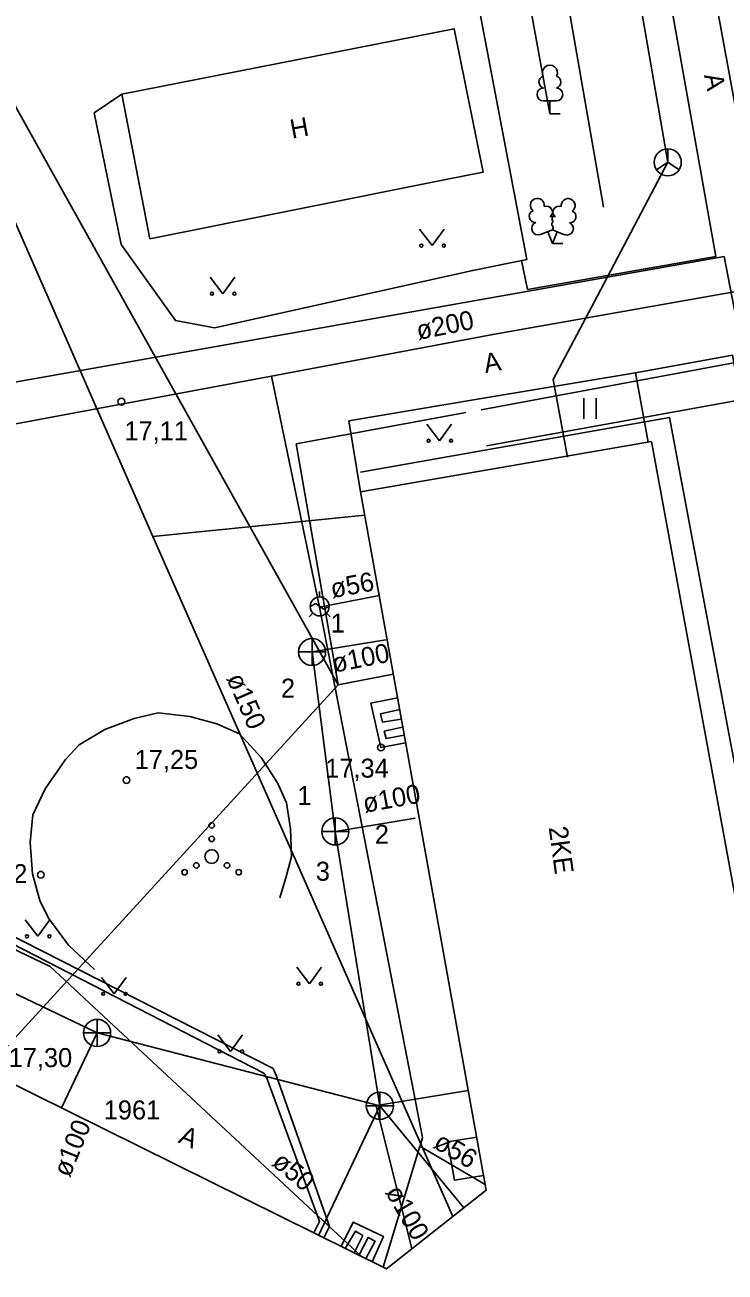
# Model space of a CAD drawing. Extents: x 713540 to 713867, y 6589774 to 6590061.
# Drawn here: x 713641.99 to 713667.81, y 6589963.85 to 6590009.83 of the extents above; entities that cross this region are included whole.
import ezdxf

# ---------------------------------------------------------------- set-up
doc = ezdxf.new("R2010")
doc.units = 0
for name, color, linetype in [('AED', 7, 'Continuous'), ('HALJASTUS', 7, 'Continuous'), ('HOONE', 7, 'Continuous'), ('HOONEDET', 7, 'Continuous'), ('KAEVU_NR', 7, 'Continuous'), ('KKAEV', 7, 'Continuous'), ('KORGUS', 7, 'Continuous'), ('KTRASS', 7, 'Continuous'), ('MPKAABEL', 7, 'Continuous'), ('PUU', 7, 'Continuous'), ('SIKAEV', 7, 'Continuous'), ('SITRASS', 7, 'Continuous'), ('TEE', 7, 'Continuous'), ('TORU NR', 7, 'Continuous'), ('TTRASS', 7, 'Continuous'), ('VTRASS', 7, 'Continuous'), ('Слой 1', 7, 'Continuous')]:
    doc.layers.add(name, color=color, linetype=linetype)

msp = doc.modelspace()

# ---------------------------------------------------------------- linework, layer by layer
at = {"layer": 'AED'}
for points in [[(713663.323, 6590003.114), (713657.209, 6590038.24)], [(713664.505, 6589997.008), (713664.975, 6589994.447)]]:
    msp.add_lwpolyline(points, dxfattribs=at)
at = {"layer": 'HALJASTUS'}
for p, q in [((713656.547, 6590002.297), (713657.01, 6590001.69)), ((713657.01, 6590001.69), (713657.456, 6590002.297)), ((713648.827, 6590000.527), (713649.29, 6589999.92)), ((713649.29, 6589999.92), (713649.736, 6590000.527)), ((713662.6, 6589996.063), (713662.6, 6589995.302)), ((713663.055, 6589996.063), (713663.055, 6589995.302)), ((713656.815, 6589995.104), (713657.278, 6589994.497)), ((713657.278, 6589994.497), (713657.724, 6589995.104)), ((713642.007, 6589976.837), (713642.47, 6589976.23)), ((713642.47, 6589976.23), (713642.916, 6589976.837)), ((713652.017, 6589975.087), (713652.48, 6589974.48)), ((713652.48, 6589974.48), (713652.926, 6589975.087)), ((713644.817, 6589974.717), (713645.28, 6589974.11)), ((713645.28, 6589974.11), (713645.726, 6589974.717)), ((713649.107, 6589972.597), (713649.57, 6589971.99)), ((713649.57, 6589971.99), (713650.016, 6589972.597))]:
    msp.add_line(p, q, dxfattribs=at)
msp.add_lwpolyline([(713655.98, 6590036), (713661.349, 6590006.549)], dxfattribs=at)
for centre, radius in [((713656.609, 6590001.69), 0.055), ((713657.438, 6590001.69), 0.055), ((713648.889, 6589999.92), 0.055), ((713649.718, 6589999.92), 0.055), ((713656.877, 6589994.497), 0.055), ((713657.706, 6589994.497), 0.055), ((713648.88, 6589980.32), 0.1), ((713648.88, 6589979.82), 0.1), ((713648.88, 6589979.17), 0.25), ((713648.315, 6589978.845), 0.1), ((713649.445, 6589978.845), 0.1), ((713647.88, 6589978.595), 0.1), ((713649.88, 6589978.595), 0.1), ((713642.069, 6589976.23), 0.055), ((713642.898, 6589976.23), 0.055), ((713652.079, 6589974.48), 0.055), ((713652.908, 6589974.48), 0.055), ((713644.879, 6589974.11), 0.055), ((713645.708, 6589974.11), 0.055), ((713649.169, 6589971.99), 0.055), ((713649.998, 6589971.99), 0.055)]:
    msp.add_circle(centre, radius, dxfattribs=at)
at = {"layer": 'HOONE'}
for p, q in [((713652.86, 6589988.74), (713652.86, 6589988.937)), ((713652.613, 6589988.143), (713652.473, 6589988.003)), ((713652.51, 6589988.388), (713652.721, 6589988.494)), ((713652.721, 6589988.494), (713652.999, 6589988.286)), ((713652.999, 6589988.286), (713653.21, 6589988.392)), ((713653.107, 6589988.143), (713653.247, 6589988.003))]:
    msp.add_line(p, q, dxfattribs=at)
for points in [[(713657.508, 6590004.134), (713646.604, 6590001.948), (713645.573, 6590007.272), (713657.824, 6590009.688), (713658.886, 6590004.404), (713657.508, 6590004.134)], [(713641.66, 6589995.12), (713651.08, 6589996.88), (713659.244, 6589998.419), (713687.328, 6590003.385)], [(713652.86, 6589988.37), (713651.08, 6589996.88)], [(713665.097, 6589994.469), (713654.36, 6589992.62), (713659, 6589966.87), (713655.32, 6589963.97), (713631.86, 6589975.579), (713626.949, 6589965.568), (713655.111, 6589952.011), (713657.717, 6589953.998), (713658.827, 6589952.543), (713664.692, 6589957.048), (713664.664, 6589957.055), (713669.225, 6589960.582), (713668.167, 6589961.969), (713670.71, 6589963.909), (713665.097, 6589994.469)], [(713655.05, 6589988.79), (713652.86, 6589988.37)], [(713656.56, 6589968.5), (713656.65, 6589968.81), (713652.86, 6589988.37)], [(713655.2, 6589964.03), (713656.55, 6589968.5)], [(713658.96, 6589967.08), (713656.55, 6589968.5)]]:
    msp.add_lwpolyline(points, dxfattribs=at)
msp.add_circle((713652.86, 6589988.39), 0.35, dxfattribs=at)
at = {"layer": 'HOONEDET'}
for points in [[(713654.365, 6589993.337), (713665.759, 6589995.354), (713671.737, 6589963.499), (713669.522, 6589961.81), (713670.612, 6589960.382), (713665.868, 6589956.768), (713665.7, 6589956.808), (713658.611, 6589951.238), (713657.507, 6589952.685), (713655.117, 6589950.862), (713625.629, 6589965.327), (713631.231, 6589977.05), (713635.106, 6589975.077), (713639.12, 6589973.07)], [(713656.03, 6589983.36), (713655.12, 6589983.19), (713654.75, 6589984.83), (713655.73, 6589985.02)], [(713655.81, 6589984.59), (713655.1, 6589984.43), (713655.18, 6589984.12), (713655.87, 6589984.24)], [(713655.92, 6589983.94), (713655.24, 6589983.79), (713655.31, 6589983.52), (713655.98, 6589983.65)], [(713658.9, 6589967.41), (713657.83, 6589967.24), (713657.57, 6589968.66), (713658.65, 6589968.83)], [(713654.8, 6589964.23), (713655.21, 6589965.16), (713654.09, 6589965.69), (713653.65, 6589964.8)], [(713654.13, 6589964.56), (713654.45, 6589965.2), (713654.18, 6589965.36), (713653.8, 6589964.72)], [(713654.56, 6589964.35), (713654.91, 6589964.99), (713654.65, 6589965.13), (713654.3, 6589964.47)]]:
    msp.add_lwpolyline(points, dxfattribs=at)
at = {"layer": 'KKAEV'}
for p, q in [((713652.58, 6589986.212), (713652.58, 6589987.212)), ((713652.08, 6589986.712), (713653.08, 6589986.712)), ((713653.437, 6589979.597), (713653.437, 6589980.597)), ((713652.937, 6589980.097), (713653.937, 6589980.097)), ((713644.655, 6589972.169), (713644.655, 6589973.169)), ((713644.155, 6589972.669), (713645.155, 6589972.669)), ((713655.079, 6589969.482), (713655.079, 6589970.482)), ((713654.579, 6589969.982), (713655.579, 6589969.982))]:
    msp.add_line(p, q, dxfattribs=at)
for centre in [(713652.58, 6589986.712), (713653.437, 6589980.097), (713644.655, 6589972.669), (713655.079, 6589969.982)]:
    msp.add_circle(centre, 0.5, dxfattribs=at)
at = {"layer": 'KORGUS'}
for centre in [(713645.55, 6589995.94), (713655.12, 6589983.19), (713645.74, 6589981.99), (713642.58, 6589978.5)]:
    msp.add_circle(centre, 0.125, dxfattribs=at)
at = {"layer": 'KTRASS'}
for points in [[(713652.58, 6589986.712), (713655.3, 6589987.16)], [(713652.58, 6589986.712), (713653.437, 6589980.097)], [(713653.437, 6589980.097), (713656.382, 6589980.582)], [(713653.437, 6589980.097), (713655.079, 6589969.982)], [(713638.256, 6589975.733), (713644.655, 6589972.669)], [(713644.655, 6589972.669), (713643.359, 6589969.931)], [(713644.655, 6589972.669), (713655.079, 6589969.982)], [(713655.113, 6589970.014), (713658.338, 6589970.545)], [(713655.079, 6589969.982), (713652.819, 6589965.207)], [(713654.943, 6589969.981), (713656.253, 6589964.705)], [(713655.079, 6589969.982), (713658.173, 6589966.219)]]:
    msp.add_lwpolyline(points, dxfattribs=at)
at = {"layer": 'MPKAABEL'}
for points in [[(713634.872, 6590060.636), (713637.296, 6590044.981), (713639.214, 6590034.99), (713641.55, 6590020.81), (713640.247, 6590018.756), (713639.99, 6590012.096), (713640.67, 6590008.54), (713653.54, 6589985.5)], [(713668.156, 6589956.222), (713674.47, 6589961.65), (713672.98, 6589971.05), (713668.19, 6589997.38), (713658.812, 6589995.642)], [(713659.015, 6589994.315), (713668.392, 6589996.01), (713673.043, 6589971.78), (713687.552, 6589973.876), (713697.295, 6589975.361), (713709.25, 6589977.48), (713710.11, 6589973.77), (713708.57, 6589973.51)], [(713658.254, 6589995.539), (713652, 6589994.38), (713653.54, 6589985.5)], [(713655.57, 6589985.89), (713653.54, 6589985.5)], [(713640.53, 6589971.3), (713653.54, 6589985.5)]]:
    msp.add_lwpolyline(points, dxfattribs=at)
at = {"layer": 'PUU'}
for p, q in [((713661.589, 6590007.024), (713661.109, 6590007.024)), ((713661.349, 6590006.549), (713661.349, 6590007.024)), ((713661.729, 6590006.549), (713661.349, 6590006.549)), ((713661.002, 6590002.099), (713661.447, 6590002.274)), ((713661.442, 6590001.764), (713661.267, 6590002.204)), ((713661.442, 6590001.764), (713661.622, 6590002.204)), ((713661.447, 6590002.274), (713661.887, 6590002.094)), ((713661.822, 6590001.764), (713661.442, 6590001.764))]:
    msp.add_line(p, q, dxfattribs=at)
msp.add_lwpolyline([(713661.447, 6590002.769), (713661.427, 6590002.694), (713661.427, 6590002.674), (713661.437, 6590002.644), (713661.457, 6590002.609), (713661.462, 6590002.589), (713661.447, 6590002.554), (713661.422, 6590002.504), (713661.417, 6590002.479), (713661.422, 6590002.464), (713661.432, 6590002.434), (713661.467, 6590002.374), (713661.472, 6590002.354), (713661.467, 6590002.334), (713661.452, 6590002.299), (713661.447, 6590002.274)], dxfattribs=at)
for centre, radius, start, end in [((713661.179, 6590007.722), 0.233, 109.0217, 253.1415), ((713661.349, 6590008.069), 0.277, 332.5799, 207.4201), ((713661.519, 6590007.722), 0.233, 286.8508, 70.9859), ((713661.112, 6590007.262), 0.238, 90.0016, 269.3953), ((713661.587, 6590007.262), 0.238, 270.6047, 89.9984), ((713660.885, 6590003.179), 0.256, 111.5027, 232.5173), ((713660.885, 6590003.179), 0.256, 350.4856, 111.5002), ((713662.021, 6590003.17), 0.256, 67.6168, 188.6314), ((713662.021, 6590003.17), 0.256, 306.5997, 67.6143), ((713660.811, 6590002.767), 0.224, 111.4304, 274.4987), ((713661.219, 6590002.928), 0.224, 308.5041, 111.5725), ((713661.683, 6590002.924), 0.225, 67.7016, 230.5126), ((713662.088, 6590002.757), 0.224, 264.6183, 67.6866), ((713660.916, 6590002.323), 0.237, 111.5014, 291.5004), ((713661.446, 6590002.532), 0.237, 66.7655, 111.5015), ((713661.977, 6590002.315), 0.237, 247.6166, 67.6155)]:
    msp.add_arc(centre, radius, start, end, dxfattribs=at)
at = {"layer": 'SIKAEV'}
for p, q in [((713665.694, 6590005.262), (713665.694, 6590004.762)), ((713665.694, 6590004.762), (713665.279, 6590004.487)), ((713665.694, 6590004.762), (713666.109, 6590004.487))]:
    msp.add_line(p, q, dxfattribs=at)
msp.add_circle((713665.694, 6590004.762), 0.5, dxfattribs=at)
at = {"layer": 'SITRASS'}
for points in [[(713634.735, 6590060.636), (713639.6, 6590031.34), (713639.42, 6590021.66), (713636.56, 6590016.77), (713638.404, 6590011.201), (713640.18, 6590005.84), (713646.71, 6589990.97), (713657.77, 6589965.9)], [(713662.189, 6590024.968), (713665.694, 6590004.762)], [(713665.694, 6590004.762), (713663.098, 6589999.845)], [(713663.098, 6589999.845), (713661.47, 6589996.76), (713661.995, 6589993.899)], [(713654.52, 6589991.75), (713646.71, 6589990.97)]]:
    msp.add_lwpolyline(points, dxfattribs=at)
at = {"layer": 'TEE'}
for points in [[(713660.517, 6590000.069), (713667.464, 6590001.287), (713661.408, 6590035.387), (713656.791, 6590060.636)], [(713643.388, 6590020.908), (713656.207, 6590023.767), (713660.498, 6590001.178), (713658.504, 6590000.777), (713648.984, 6589998.66), (713647.543, 6589998.927), (713645.546, 6590001.73), (713644.549, 6590006.589), (713645.573, 6590007.272)], [(713660.517, 6590000.069), (713660.302, 6590001.139)], [(713674.64, 6589955.464), (713675.571, 6589956.424), (713670.734, 6589983.028), (713668.075, 6589997.658), (713664.505, 6589997.008), (713658.749, 6589996.047), (713653.94, 6589995.227), (713654.36, 6589992.62)], [(713644.561, 6589975.01), (713643.599, 6589975.909), (713642.868, 6589976.896), (713642.544, 6589977.552), (713642.271, 6589978.53), (713642.186, 6589979.688), (713642.28, 6589980.71), (713642.746, 6589981.662), (713643.49, 6589982.747), (713643.992, 6589983.287), (713644.94, 6589983.853), (713646.024, 6589984.255), (713646.901, 6589984.467), (713648.071, 6589984.328), (713649.07, 6589984.06), (713649.906, 6589983.696), (713650.703, 6589982.817), (713651.3, 6589981.89), (713651.636, 6589981.152), (713651.788, 6589980.196), (713651.824, 6589979.172), (713651.643, 6589978.471), (713651.398, 6589977.649)]]:
    msp.add_lwpolyline(points, dxfattribs=at)
at = {"layer": 'TTRASS'}
for points in [[(713628.896, 6590060.636), (713628.908, 6590060.564), (713631.035, 6590048.786), (713632.894, 6590037.061), (713635.242, 6590025.21), (713636.781, 6590013.249), (713637.307, 6590001.316), (713637.157, 6589996.645), (713637.245, 6589996.6), (713639.784, 6589996.778), (713639.911, 6589996.659), (713640.338, 6589988.697), (713640.169, 6589976.679), (713640.253, 6589976.609), (713650.804, 6589971.182), (713650.915, 6589970.999), (713652.857, 6589965.719), (713652.647, 6589965.295)], [(713629.199, 6590060.636), (713631.21, 6590049.147), (713633.256, 6590037.367), (713635.386, 6590025.437), (713637.081, 6590013.496), (713637.406, 6590001.507), (713637.495, 6589997.061), (713637.616, 6589996.981), (713640.19, 6589997.018), (713640.241, 6589996.932), (713640.549, 6589988.818), (713640.423, 6589976.86), (713640.479, 6589976.779), (713651.149, 6589971.354), (713651.264, 6589971.081), (713653.226, 6589965.534), (713653.017, 6589965.111)]]:
    msp.add_lwpolyline(points, dxfattribs=at)
at = {"layer": 'VTRASS'}
for points in [[(713684.308, 6589921.181), (713683.129, 6589927.373), (713681.203, 6589936.836), (713678.244, 6589950.963), (713676.229, 6589960.85), (713673.946, 6589973.712), (713673.362, 6589976.754), (713673.233, 6589977.362), (713672.25, 6589983.027), (713670.156, 6589996.06), (713667.268, 6590011.807), (713664.478, 6590027.857), (713664.208, 6590029.493), (713663.195, 6590035.091), (713660.78, 6590048.281), (713658.62, 6590060.636)], [(713608.676, 6589956.662), (713621.51, 6589985.36), (713642.92, 6589975.12), (713654.41, 6589964.42)]]:
    msp.add_lwpolyline(points, dxfattribs=at)
at = {"layer": 'Слой 1'}
msp.add_lwpolyline([(713667.77, 6590001.29), (713675.57, 6589961), (713658.19, 6589946.81), (713619.46, 6589962.4), (713633.01, 6589995.13)], close=True, dxfattribs=at)

# ---------------------------------------------------------------- texts
at = {"layer": 'HOONE'}
for s, rotation, p in [('H', 10.7425, (713651.841, 6590005.631)), ('2KE', 277.733, (713661.302, 6589980.243))]:
    msp.add_text(s, height=0.7, rotation=rotation, dxfattribs=at).set_placement(p)
at = {"layer": 'KAEVU_NR'}
msp.add_text('1961', height=0.7, dxfattribs=at).set_placement((713644.9, 6589969.48))
at = {"layer": 'KORGUS'}
for s, p in [('17,11', (713645.662, 6589994.515)), ('17,25', (713646.041, 6589982.4)), ('17,34', (713653.064, 6589982.08)), ('17,22', (713639.743, 6589978.19)), ('17,30', (713641.395, 6589971.41))]:
    msp.add_text(s, height=0.7, dxfattribs=at).set_placement(p)
at = {"layer": 'TEE'}
for rotation, p in [(281.572, (713667.028, 6590007.972)), (10.0829, (713658.974, 6589996.995)), (336.3948, (713647.61, 6589968.64))]:
    msp.add_text('A', height=0.7, rotation=rotation, dxfattribs=at).set_placement(p)
at = {"layer": 'TORU NR'}
for s, rotation, p in [('ø200', 11.2551, (713656.5, 6589998.212)), ('ø56', 10.4375, (713653.325, 6589988.693)), ('ø100', 11.2188, (713653.389, 6589985.945)), ('ø150', 293.4985, (713649.413, 6589985.747)), ('ø100', 10.356, (713654.518, 6589980.78)), ('ø100', 67.8548, (713643.643, 6589967.31)), ('ø56', 329.2301, (713657.008, 6589968.467)), ('ø50', 319.9138, (713651.058, 6589967.823)), ('ø100', 299.9084, (713655.261, 6589966.805))]:
    msp.add_text(s, height=0.7, rotation=rotation, dxfattribs=at).set_placement(p)
for s, p in [('1', (713653.268, 6589987.43)), ('2', (713651.434, 6589985.03)), ('1', (713652.038, 6589981.07)), ('2', (713654.894, 6589979.64)), ('3', (713652.719, 6589978.28))]:
    msp.add_text(s, height=0.7, dxfattribs=at).set_placement(p)

doc.saveas('drawing.dxf')
